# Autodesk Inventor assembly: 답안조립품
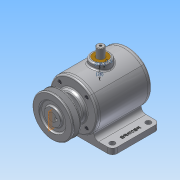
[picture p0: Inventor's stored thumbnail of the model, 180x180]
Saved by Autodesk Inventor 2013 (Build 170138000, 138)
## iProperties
Created: 2015-08
Part Number: 답안조립품
Document SubType Name: Assembly
Designer: Administrator
Mass: 2990.33 g
Surface Area: 2017.36 cm^2
Volume: 938.374 cm^3
Density: 3.18671 g/cm^3
Author: Administrator
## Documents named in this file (14)
- C:\Users\Administrator\Desktop\350806V1025\답안조립품.iam
- C:\Users\Administrator\Desktop\350806V1025\KS B 1028  - 납작점M4x5.ipt
- C:\Users\Administrator\Desktop\350806V1025\KS B 1311 - 5 x 5 x 18I.ipt
- C:\Users\Administrator\Desktop\350806V1025\M4-소켓머리.ipt
- C:\Users\Administrator\Desktop\350806V1025\V-벨트풀리.ipt
- C:\Users\Administrator\Desktop\350806V1025\뒷커버.ipt
- C:\Users\Administrator\Desktop\350806V1025\베어링 6203.ipt
- C:\Users\Administrator\Desktop\350806V1025\본체.ipt
- C:\Users\Administrator\Desktop\350806V1025\부시.ipt
- C:\Users\Administrator\Desktop\350806V1025\스프링1 [가변부품].ipt
- C:\Users\Administrator\Desktop\350806V1025\슬라이더.ipt
- C:\Users\Administrator\Desktop\350806V1025\앞커버.ipt
- C:\Users\Administrator\Desktop\350806V1025\오일실.ipt
- C:\Users\Administrator\Desktop\350806V1025\축.ipt
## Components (14 placed, 6 different names)
1. KS B 1028 납작점 - 미터 납작점M4x5:1
2. KS B 1311 (I) 5 x 5 x 18:1
3. V-벨트풀리:1 — 플러쉬:2
4. 7-베어링 6203:1
5. 8-오일실:1
6. 7-베어링 6203:2
7. 9-M4-소켓머리:1
8. 9-M4-소켓머리:3
9. 9-M4-소켓머리:4
10. 9-M4-소켓머리:5
11. 9-M4-소켓머리:2
12. 9-M4-소켓머리:6
13. 9-M4-소켓머리:7
14. 9-M4-소켓머리:8
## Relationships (1: Flush 1)
- 플러쉬:2 [Flush]: V-벨트풀리:1
